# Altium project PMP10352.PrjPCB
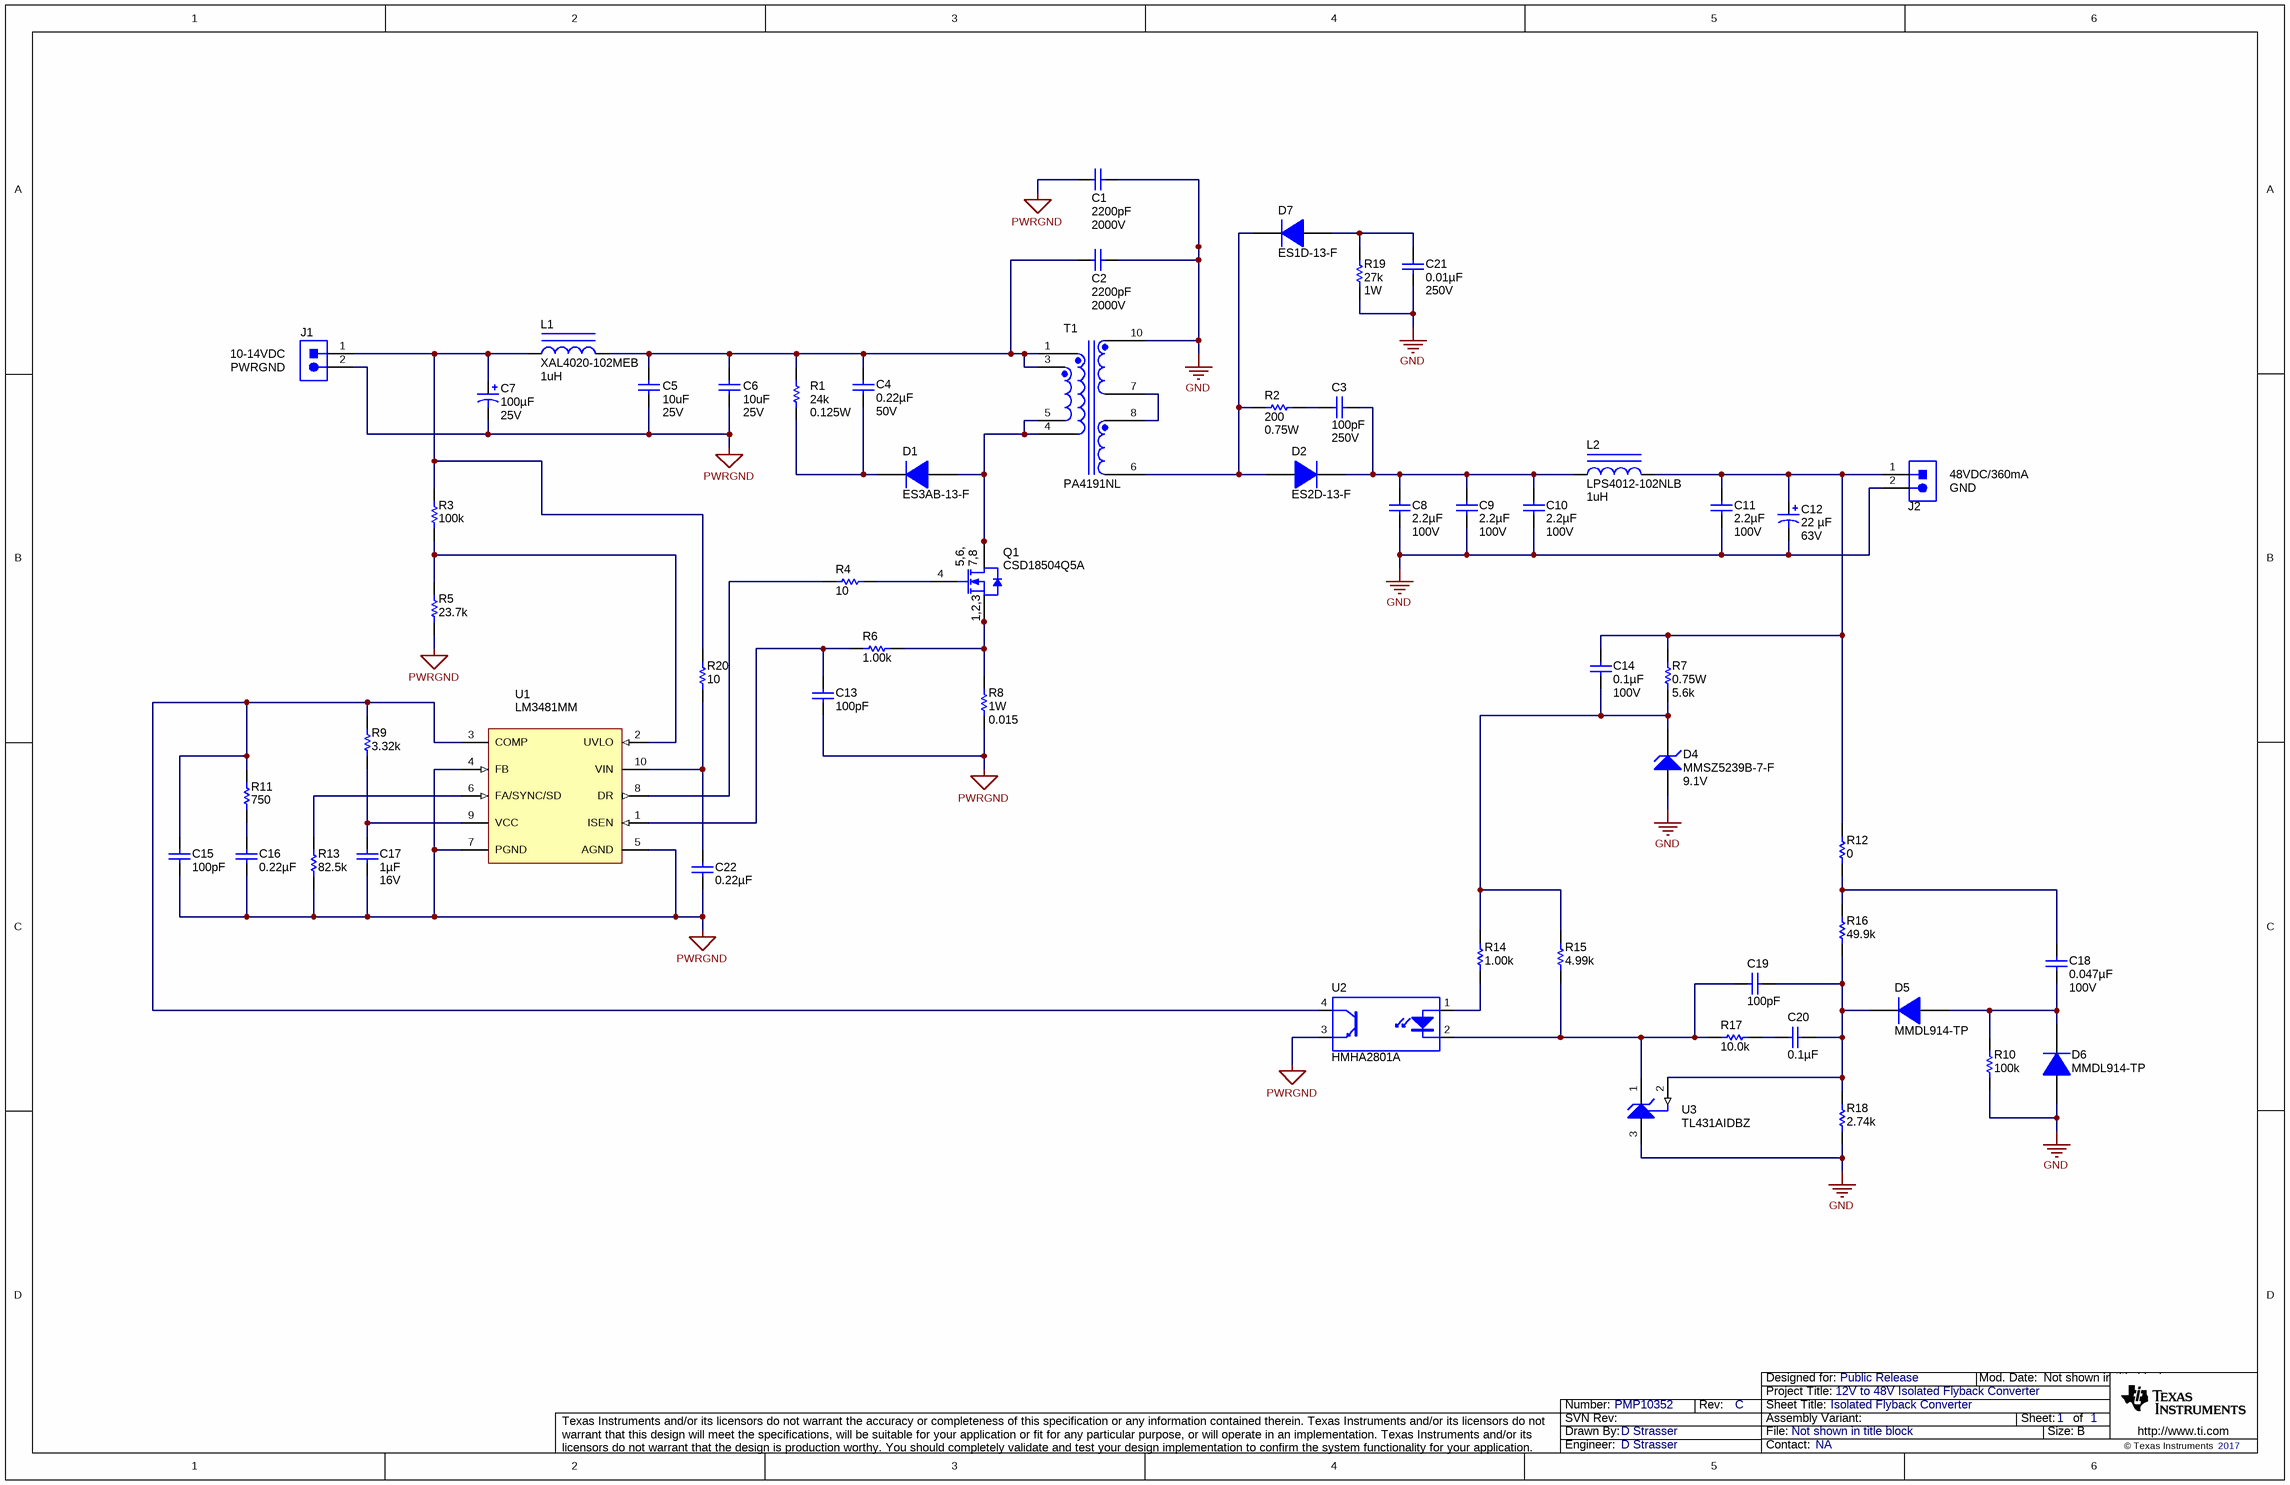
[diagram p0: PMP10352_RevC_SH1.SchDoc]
TechSupport: NA; SCH_Rev: C; PRJ_Title: 12V to 48V Isolated Flyback Converter; PRJ_Number: PMP10352; PRJ_Engineer: D Strasser; PRJ_Customer: Public Release; PCB_Rev: C; PCB_Layout: D Strasser; CopyrightYear: 2017
1 sheet, 57 parts. Net scope: global (net labels, ports and power ports of the same name join across sheets).
Board file: PMP10352_RevC.PcbDoc

## Sheet PMP10352_RevC_SH1.SchDoc: Isolated Flyback Converter
size 431 x 279 mm; Date: Not shown in title block; ApprovedBy: Not shown in title block; CheckedBy: Not shown in title block; Author: Not shown in title block; CompanyName: Not shown in title block; DrawnBy: D Strasser; Engineer: Not shown in title block; Organization: Not shown in title block; Address1: Not shown in title block; Address2: Not shown in title block; Address3: Not shown in title block; Address4: Not shown in title block; DocumentNumber: 1; Revision: Use project parameter SCH_Rev; SheetNumber: 1; SheetTotal: 1; PageSetup: Record=PageOptions¦CenterHorizontal=True¦CenterVertical=True¦PrintScale=1.00¦XCorrection=1.00¦YCorrection=1.00¦PrintKind=0¦BorderSize=5000000¦LeftOffset=0¦BottomOffset=0¦Orientation=2¦PaperLength=1000¦PaperWidth=1000¦Scale=100¦PaperSource=15¦PrintQuality=600¦MediaType=1¦DitherType=10¦PaperKind=Letter¦PrintScaleMode=1

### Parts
C1  ValueDisplayed: 2200pF  Value2: 2000V  [1812L]  (hidden comment: C4532X7R3D222K)
C2  ValueDisplayed: 2200pF  Value2: 2000V  [1812L]  (hidden comment: C4532X7R3D222K)
C3  ValueDisplayed: 100pF  Value2: 250V  [0805_HV]  (hidden comment: GRM21A5C2E101JW01D)
C4  ValueDisplayed: 0.22µF  Value2: 50V  [0805L]  (hidden comment: C2012X7R1H224K)
C5  value 10uF  Value2: 25V  [1210L]  (hidden comment: C3225X7R1E106K)
C6  value 10uF  Value2: 25V  [1210L]  (hidden comment: C3225X7R1E106K)
C7  ValueDisplayed: 100µF  Value2: 25V  [SM_RADIAL_D8]  (hidden comment: EEE-FK1E101XP)
C8  ValueDisplayed: 2.2µF  Value2: 100V  [1210L]  (hidden comment: GRM32ER72A225KA35L)
C9  ValueDisplayed: 2.2µF  Value2: 100V  [1210L]  (hidden comment: GRM32ER72A225KA35L)
C10  ValueDisplayed: 2.2µF  Value2: 100V  [1210L]  (hidden comment: GRM32ER72A225KA35L)
C11  ValueDisplayed: 2.2µF  Value2: 100V  [1210L]  (hidden comment: GRM32ER72A225KA35L)
C12  ValueDisplayed: 22 µF  Value2: 63V  [SM_RADIAL_D8]  (hidden comment: EEE-FK1J220XP)
C13  ValueDisplayed: 100pF  [0603L]  (hidden comment: C1608C0G1H101J)
C14  ValueDisplayed: 0.1µF  Value2: 100V  [0805_HV]  (hidden comment: C2012X7R2A104K125AA)
C15  ValueDisplayed: 100pF  [0603L]  (hidden comment: C1608C0G1H101J)
C16  ValueDisplayed: 0.22µF  [0603L]  (hidden comment: C1608X7R1E224K080AC)
C17  ValueDisplayed: 1µF  Value2: 16V  [0603L]  (hidden comment: C1608X7R1C105K080AC)
C18  ValueDisplayed: 0.047µF  Value2: 100V  [0805_HV]  (hidden comment: C2012X7R2A473K125AA)
C19  ValueDisplayed: 100pF  [0603L]  (hidden comment: C1608C0G1H101J)
C20  ValueDisplayed: 0.1µF  [0603L]  (hidden comment: C1608X7R1E104K080AA)
C21  ValueDisplayed: 0.01µF  Value2: 250V  [0805_HV]  (hidden comment: GRM21BR72E103KW03L)
C22  ValueDisplayed: 0.22µF  [0603L]  (hidden comment: C1608X7R1E224K080AC)
D1  ES3AB-13-F  [SMB]
D2  ES2D-13-F  [SMB]
D4  MMSZ5239B-7-F  value 9.1V  [SOD-123]
D5  MMDL914-TP  [sod-323]
D6  MMDL914-TP  [sod-323]
D7  ES1D-13-F  [SMA]
J1  PEC02SAAN  [CONN_PEC02SAAN]  (value not drawn)
J2  PEC02SAAN  [CONN_PEC02SAAN]  (value not drawn)
L1  XAL4020-102MEB  value 1uH  [XAL4020]
L2  LPS4012-102NLB  value 1uH  [LPS4012]
Q1  CSD18504Q5A  [TRANS_NexFET_Q5A]
R1  value 24k  Value2: 0.125W  [0805L]  (hidden comment: CRCW080524K0JNEA)
R2  value 200  Value2: 0.75W  [2010L]  (hidden comment: CRCW2010200RJNEF)
R3  value 100k  [0603L]  (hidden comment: CRCW0603100KFKEA)
R4  ValueDisplayed: 10  [0603]  (hidden comment: CRCW060310R0JNEA)
R5  value 23.7k  [0603L]  (hidden comment: CRCW060323K7FKEA)
R6  value 1.00k  [0603L]  (hidden comment: CRCW06031K00FKEA)
R7  Value2: 0.75W  ValueDisplayed: 5.6k  [2010]  (hidden comment: CRCW20105K60JNEF)
R8  Value2: 1W  ValueDisplayed: 0.015  [2010]  (hidden comment: CSRN2010FK15L0)
R9  value 3.32k  [0603L]  (hidden comment: CRCW06033K32FKEA)
R10  ValueDisplayed: 100k  [0603L]  (hidden comment: CRCW0603100KFKEA)
R11  ValueDisplayed: 750  [0603L]  (hidden comment: CRCW0603750RFKEA)
R12  value 0  [0603L]  (hidden comment: ERJ-3GEY0R00V)
R13  value 82.5k  [0603L]  (hidden comment: CRCW060382K5FKEA)
R14  value 1.00k  [0603L]  (hidden comment: CRCW06031K00FKEA)
R15  value 4.99k  [0603L]  (hidden comment: CRCW06034K99FKEA)
R16  value 49.9k  [0603L]  (hidden comment: CRCW060349K9FKEA)
R17  value 10.0k  [0603L]  (hidden comment: CRCW060310K0FKEA)
R18  value 2.74k  [0603L]  (hidden comment: CRCW06032K74FKEA)
R19  value 27k  Value2: 1W  [2512]  (hidden comment: CRCW251227K0JNEG)
R20  ValueDisplayed: 10  [0603L]  (hidden comment: CRCW060310R0JNEA)
T1  PA4191NL  [PULSE_PA4191NL]
U1  LM3481MM  [MUB10A_N]
U2  HMHA2801A  [MFP04A]
U3  TL431AIDBZ  [DBZ0003A_L]

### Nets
GND: C1.1 C2.1 C8.2 C9.2 C10.2 C11.2 C12.2(-) C21.2 D4.2(A) D6.2(A) J2.2 R10.1 R18.1 R19.1 T1.10 U3.3(ANODE)
PWRGND: C1.2 C5.2 C6.2 C7.2(-) C13.2 C15.2 C16.2 C17.2 C22.2 J1.2 R5.1 R8.1 R13.1 U1.4(FB) U1.5(AGND) U1.7(PGND) U2.3(E)
NetC2_2: C2.2 C4.1 C5.1 C6.1 L1.2 R1.2 T1.1 T1.3
NetC3_1: C3.1 C8.1 C9.1 C10.1 D2.1(K) L2.1
NetC3_2: C3.2 R2.2
NetC4_2: C4.2 D1.1(K) R1.1
NetC7_1: C7.1(+) J1.1 L1.1 R3.2 R20.2
NetC11_1: C11.1 C12.1(+) C14.1 J2.1 L2.2 R7.2 R12.2
NetC13_1: C13.1 R6.2 U1.1(ISEN)
NetC14_2: C14.2 D4.1(K) R7.1 R14.2 R15.2
NetC15_1: C15.1 R9.2 R11.2 U1.3(COMP) U2.4(C)
NetC16_1: C16.1 R11.1
NetC17_1: C17.1 R9.1 U1.9(VCC)
NetC18_1: C18.1 R12.1 R16.2
NetC18_2: C18.2 D5.2(A) D6.1(K) R10.2
NetC19_1: C19.1 C20.1 D5.1(K) R16.1 R18.2 U3.2(REF)
NetC19_2: C19.2 R15.1 R17.2 U2.2(K) U3.1(CATHODE)
NetC20_2: C20.2 R17.1
NetC21_1: C21.1 D7.2(A) R19.2
NetC22_1: C22.1 R20.1 U1.10(VIN)
NetD1_2: D1.2(A) Q1.5(D) Q1.6(D) Q1.7(D) Q1.8(D) Q1.9(D) T1.4 T1.5
NetD2_2: D2.2(A) D7.1(K) R2.1 T1.6
NetQ1_1: Q1.1(S) Q1.2(S) Q1.3(S) R6.1 R8.2
NetQ1_4: Q1.4(G) R4.2
NetR3_1: R3.1 R5.2 U1.2(UVLO)
NetR4_1: R4.1 U1.8(DR)
NetR13_2: R13.2 U1.6(FA/SYNC/SD)
NetR14_1: R14.1 U2.1(A)
NetT1_7: T1.7 T1.8

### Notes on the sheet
- (near J1) 10-14VDC
- (near J1) PWRGND
- (near J2) 48VDC/360mA
- (near J2) GND

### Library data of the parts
C1 C2 = C4532X7R3D222K: CAP, CERM, 2200pF, 2000V, +/-10%, X7R, 1812; Manufacturer: TDK; Polarized: N; CompType: Capacitor; U/M: EA; Cap_F: 0.0000000022; Tolerance_%: 10; Value1: Unknown; VDC_V: 2000; TaMin_C: -55; TaMax_C: 125; Cap_Case: 1812
C3 = GRM21A5C2E101JW01D: CAP, CERM, 100 pF, 250 V, +/- 5%, C0G/NP0, 0805; Manufacturer: MuRata; Polarized: N; CompType: Capacitor; Value: 100pF; U/M: EA; Cap_F: 0.0000000001; Tolerance_%: 5; Value1: Unknown; VDC_V: 250; TaMin_C: -55; TaMax_C: 125; Cap_Case: 0805
C4 = C2012X7R1H224K: CAP, CERM, 0.22uF, 50V, +/-10%, X7R, 0805; Manufacturer: TDK; Polarized: N; CompType: Capacitor; U/M: EA; Cap_F: 0.00000022; Tolerance_%: 10; ESR_Ohm: 0.0117; Value1: 0.0117 ohm; VDC_V: 50; TaMin_C: -55; TaMax_C: 125; Cap_Case: 0805
C5 C6 = C3225X7R1E106M: CAP, CERM, 10uF, 25V, +/-20%, X7R, 1210; Manufacturer: TDK; Polarized: N; CompType: Capacitor; ValueDisplayed: 10µF; U/M: EA; Cap_F: 0.00001; Tolerance_%: 20; ESR_Ohm: 0.0027; Value1: 0.0027 ohm; VDC_V: 25; IRMS_A: 3; TaMin_C: -55; TaMax_C: 125; Cap_Case: 1210
C7 = EEE-FK1E101XP: CAP, AL, 100uF, 25V, +/-20%, 0.34 ohm, SMD; Manufacturer: Panasonic; Polarized: Y; CompType: Capacitor; U/M: EA; Cap_F: 0.0001; Tolerance_%: 20; VDC_V: 25; ESR_Ohm: 0.34; IRMS_A: 0.28; TaMin_C: -55; TaMax_C: 105; Cap_Case: D8
C8-C11 = GRM32ER72A225KA35L: CAP, CERM, 2.2uF, 100V, +/-10%, X7R, 1210; Manufacturer: MuRata; Polarized: N; CompType: Capacitor; U/M: EA; Cap_F: 0.0000022; Tolerance_%: 10; ESR_Ohm: 0.007; Value1: 0.007 ohm; VDC_V: 100; IRMS_A: 4.4; TaMin_C: -55; TaMax_C: 125; Cap_Case: 1210
C12 = EEE-FK1J220XP: CAP, AL, 22uF, 63V, +/-20%, 1.2 ohm, SMD; Manufacturer: Panasonic; Polarized: Y; CompType: Capacitor; U/M: EA; Cap_F: 0.000022; Tolerance_%: 20; Value1: 1.2 ohm; VDC_V: 63; ESR_Ohm: 1.2; IRMS_A: 0.12; TaMin_C: -55; TaMax_C: 105; Cap_Case: D8
C13 C15 C19 = C1608C0G1H101J: CAP, CERM, 100pF, 50V, +/-5%, C0G/NP0, 0603; Manufacturer: TDK; Polarized: N; CompType: Capacitor; U/M: EA; Cap_F: 0.0000000001; Tolerance_%: 5; ESR_Ohm: 0.1679; Value1: 0.1679 ohm; VDC_V: 50; TaMin_C: -55; TaMax_C: 125; Cap_Case: 0603
C14 = C2012X7R2A104K125AA: CAP, CERM, 0.1 µF, 100 V,+/- 10%, X7R, 0805; Manufacturer: TDK; Polarized: N; CompType: Capacitor; Value: 0.1uF; U/M: EA; Cap_F: 0.0000001; Tolerance_%: 10; ESR_ohm: 0.020726; Value1: 0.020726 ohm; VDC_V: 100; IRMS_A: 1.456; TaMin_C: -55; TaMax_C: 125; Cap_Case: 0805; SizeArea_mm2: 2.5; SizeAreaWB_mm2: 6.75; SizeX_mm: 2; SizeY_mm: 1.25; SizeZ_mm: 1.45; AEC Category: Q200; Green_Lifecycle: Active; Green_REACh: Passed
C16 C22 = C1608X7R1E224K080AC: CAP, CERM, 0.22 µF, 25 V,+/- 10%, X7R, 0603; Manufacturer: TDK; Polarized: N; CompType: Capacitor; Value: 0.22uF; U/M: EA; Cap_F: 0.00000022; Tolerance_%: 10; VDC_V: 25; Value2: 25V; TaMin_C: -55; TaMax_C: 125; Cap_Case: 0603; SizeArea_mm2: 1.28; SizeAreaWB_mm2: 4.68; SizeX_mm: 1.6; SizeY_mm: 0.8; SizeZ_mm: 1; AEC Category: Q200
C17 = C1608X7R1C105K080AC: CAP, CERM, 1 µF, 16 V,+/- 10%, X7R, 0603; Manufacturer: TDK; Polarized: N; CompType: Capacitor; Value: 1uF; U/M: EA; Cap_F: 0.000001; Tolerance_%: 10; ESR_ohm: 0.0057; Value1: 0.0057 ohm; VDC_V: 16; TaMin_C: -55; TaMax_C: 125; Cap_Case: 0603; SizeArea_mm2: 1.28; SizeAreaWB_mm2: 4.68; SizeX_mm: 1.6; SizeY_mm: 0.8; SizeZ_mm: 1; AEC Category: Q200; Green_Lifecycle: Active; Green_REACh: Passed
C18 = C2012X7R2A473K125AA: CAP, CERM, 0.047 µF, 100 V,+/- 10%, X7R, 0805; Manufacturer: TDK; Polarized: N; CompType: Capacitor; Value: 0.047uF; U/M: EA; Cap_F: 0.000000047; Tolerance_%: 10; ESR_ohm: 0.049089; Value1: 0.049089 ohm; VDC_V: 100; IRMS_A: 0.963171; TaMin_C: -55; TaMax_C: 125; Cap_Case: 0805; SizeArea_mm2: 2.5; SizeAreaWB_mm2: 6.75; SizeX_mm: 2; SizeY_mm: 1.25; SizeZ_mm: 1.45; AEC Category: Q200
C20 = C1608X7R1E104K080AA: CAP, CERM, 0.1 µF, 25 V,+/- 10%, X7R, 0603; Manufacturer: TDK; Polarized: N; CompType: Capacitor; Value: 0.1uF; U/M: EA; Cap_F: 0.0000001; Tolerance_%: 10; VDC_V: 25; Value2: 25V; TaMin_C: -55; TaMax_C: 125; Cap_Case: 0603; SizeArea_mm2: 1.28; SizeAreaWB_mm2: 4.68; SizeX_mm: 1.6; SizeY_mm: 0.8; SizeZ_mm: 1; AEC Category: Q200; Green_Lifecycle: NRND; Green_REACh: Passed
C21 = GRM21BR72E103KW03L: CAP, CERM, 0.01 µF, 250 V,+/- 10%, X7R, 0805; Manufacturer: MuRata; Polarized: N; CompType: Capacitor; Value: 0.01uF; U/M: EA; Cap_F: 0.00000001; Tolerance_%: 10; VDC_V: 250; TaMin_C: -55; TaMax_C: 125; Cap_Case: 0805; SizeArea_mm2: 2.5; SizeAreaWB_mm2: 6.75; SizeX_mm: 2; SizeY_mm: 1.25; SizeZ_mm: 1.45; AEC Category: Q200; Green_Lifecycle: Not Set; Green_REACh: Incomplete
D1 = ES3AB-13-F: Diode, Superfast Rectifier, 50V, 3A, SMB; Manufacturer: Diodes Inc.; U/M: EA; Vf_V: 0.9; Value2: 0.9V; Io_A: 3; Vr_V: 50; TJmax_C: 150; RJC_CperW: 10
D2 = ES2D-13-F: Diode, Ultrafast, 200V, 2A, SMB; Manufacturer: Diodes Inc.; U/M: EA; Vf_V: 0.92; Value2: 0.92V; Io_A: 2; Vr_V: 200; TJmax_C: 150; RJC_CperW: 20
D4 = MMSZ5239B-7-F: Diode, Zener, 9.1V, 500mW, SOD-123; Manufacturer: Diodes Inc.; SymbolCreator: a0412235; U/M: EA; Power_W: 0.5; Vz_V: 9.1; Value1: 0.5W; RJA_CperW: 350
D5 D6 = MMDL914-TP: Diode, Switching, 100V, 0.2A, SOD-323; Manufacturer: Micro Commercial Components; U/M: EA; Vf_V: 1; Value2: 1V; Io_A: 0.2; Vr_V: 100; TJmax_C: 150; RJC_CperW: 635
D7 = ES1D-13-F: Diode, Ultrafast, 200V, 1A, SMA; Manufacturer: Diodes Inc.; U/M: EA; Vf_V: 0.92; Value2: 0.92V; Io_A: 1; Vr_V: 200; TJmax_C: 150; RJC_CperW: 25
J1 J2 = PEC02SAAN: Header, 100mil, 2x1, Tin, TH; Manufacturer: Sullins Connector Solutions; SymbolCreator: a0412235; U/M: EA
L1 = XAL4020-102MEB: Inductor, Shielded, Composite, 1uH, 8.75A, 0.01 ohm, SMD; Manufacturer: Coilcraft; Ind_H: 1.0E-6; ValueDisplayed: 1µH; Imax_A: 8.75; Irms: 9.6A @ 40C rise; Isat: 8.75A @ 30% inductance drop; DCR_ohm: 0.01
L2 = LPS4012-102NLB: Inductor, Shielded Drum Core, Ferrite, 1uH, 2.4A, 0.06 ohm, SMD; Manufacturer: Coilcraft; Ind_H: 1.0E-6; ValueDisplayed: 1µH; Imax_A: 2.4; Irms: 2.4A @ 40C rise; Isat: 3A @ 30% inductance drop; DCR_ohm: 0.06
Q1 = CSD18504Q5A: MOSFET, N-CH, 40V, 15A, SON 5x6mm; Manufacturer: Texas Instruments; Alternate Manufacturer: None; U/M: EA; ChType: N; VdsMax_V: 40; Value1: 0.0098 ohm; Rdson45_Ohm: 0.0098; Value2: 7.7 nC; QgTyp_nC: 7.7; Vgs_V: 20; IdsMax_A: 15
R1 = CRCW080524K0JNEA: RES, 24k ohm, 5%, 0.125W, 0805; Manufacturer: Vishay-Dale; CompType: Resistor; Res_ohm: 24000; Value_Code: 24k0; Tolerance_%: 5; Power_W: 0.125; VDC_V: 150; TempCo: 200 ppm/C; EIA_Code: E24; U/M: EA
R2 = CRCW2010200RJNEF: RES, 200 ohm, 5%, 0.75W, 2010; Manufacturer: Vishay-Dale; CompType: Resistor; Value_Code: 200R; Tolerance_%: 5; Power_W: 0.75; VDC_V: 400; TempCo: 200 ppm/C; EIA_Code: E24; U/M: EA
R3 = CRCW0603100KFKEA: RES, 100k ohm, 1%, 0.1W, 0603; Manufacturer: Vishay-Dale; CompType: Resistor; Res_ohm: 100000; Tolerance_%: 1; Power_W: 0.1; VDC_V: 75; TempCo: 100 ppm/C; EIA_Code: E96; U/M: EA
R4 R20 = CRCW060310R0JNEA: RES, 10, 5%, 0.1 W, 0603; Manufacturer: Vishay-Dale; CompType: Resistor; Value: 10; Value_Code: 10R0; Tolerance_%: 5; Power_W: 0.1; Value2: 0.1W; VDC_V: 75; TempCo: 200 ppm/C; EIA_Code: E24; U/M: EA; SizeArea_mm2: 1.28; SizeX_mm: 1.6; SizeY_mm: 0.8; SizeZ_mm: 1; AEC Category: Q200; Green_Lifecycle: Active; Green_REACh: Passed
R5 = CRCW060323K7FKEA: RES, 23.7k ohm, 1%, 0.1W, 0603; Manufacturer: Vishay-Dale; CompType: Resistor; Res_ohm: 23700; Value_Code: 23k7; Tolerance_%: 1; Power_W: 0.1; VDC_V: 75; TempCo: 100 ppm/C; EIA_Code: E96; U/M: EA
R6 R14 = CRCW06031K00FKEA: RES, 1.00k ohm, 1%, 0.1W, 0603; Manufacturer: Vishay-Dale; CompType: Resistor; Res_ohm: 1000; Value_Code: 1k00; Tolerance_%: 1; Power_W: 0.1; VDC_V: 75; TempCo: 100 ppm/C; EIA_Code: E96; U/M: EA
R7 = CRCW20105K60JNEF: RES, 5.6 k, 5%, 0.75 W, AEC-Q200 Grade 0, 2010; Manufacturer: Vishay-Dale; CompType: Resistor; Value: 5.6k; Res_ohm: 5600; Value_Code: 5k60; Tolerance_%: 5; Power_W: 0.75; VDC_V: 400; TempCo: 200 ppm/C; EIA_Code: E24; U/M: EA; SizeArea_mm2: 12.5; SizeY_mm: 2.5; SizeZ_mm: 1.66; AEC Category: Q200; AEC Qualified: Y; AEC Grade: 0
R8 = CSRN2010FK15L0: RES, 0.015, 1%, 1 W, 2010; Manufacturer: Stackpole Electronics Inc; CompType: Resistor; Value: 0.015; Value_Code: R015; Tolerance_%: 1; TempCo: 250 ppm/C; EIA_Code: E96; U/M: EA; SizeArea_mm2: 12.5; SizeX_mm: 5; SizeY_mm: 2.5; SizeZ_mm: 1.66; AEC Category: Q200
R9 = CRCW06033K32FKEA: RES, 3.32k ohm, 1%, 0.1W, 0603; Manufacturer: Vishay-Dale; CompType: Resistor; Res_ohm: 3320; Value_Code: 3k32; Tolerance_%: 1; Power_W: 0.1; VDC_V: 75; TempCo: 100 ppm/C; EIA_Code: E96; U/M: EA
R10 = CRCW0603100KFKEA: RES, 100 k, 1%, 0.1 W, 0603; Manufacturer: Vishay-Dale; CompType: Resistor; Value: 100k; Res_ohm: 100000; Tolerance_%: 1; Power_W: 0.1; Value2: 0.1W; VDC_V: 75; TempCo: 100 ppm/C; EIA_Code: E96; U/M: EA; SizeArea_mm2: 1.28; SizeX_mm: 1.6; SizeY_mm: 0.8; AEC Category: Q200; Green_Lifecycle: Active; Green_REACh: Passed
R11 = CRCW0603750RFKEA: RES, 750, 1%, 0.1 W, 0603; Manufacturer: Vishay-Dale; CompType: Resistor; Value_Code: 750R; Tolerance_%: 1; Power_W: 0.1; Value2: 0.1W; VDC_V: 75; TempCo: 100 ppm/C; EIA_Code: E96; U/M: EA; Value: 750
R12 = ERJ-3GEY0R00V: RES, 0 ohm, 5%, 0.1W, 0603; Manufacturer: Panasonic; CompType: Resistor; Value_Code: 0000; Tolerance_%: 5; Power_W: 0.1; VDC_V: 50; TempCo: 600 ppm/C; EIA_Code: E24; U/M: EA
R13 = CRCW060382K5FKEA: RES, 82.5k ohm, 1%, 0.1W, 0603; Manufacturer: Vishay-Dale; CompType: Resistor; Res_ohm: 82500; Value_Code: 82k5; Tolerance_%: 1; Power_W: 0.1; VDC_V: 75; TempCo: 100 ppm/C; EIA_Code: E96; U/M: EA
R15 = CRCW06034K99FKEA: RES, 4.99k ohm, 1%, 0.1W, 0603; Manufacturer: Vishay-Dale; CompType: Resistor; Res_ohm: 4990; Value_Code: 4k99; Tolerance_%: 1; Power_W: 0.1; VDC_V: 75; TempCo: 100 ppm/C; EIA_Code: E96; U/M: EA
R16 = CRCW060349K9FKEA: RES, 49.9k ohm, 1%, 0.1W, 0603; Manufacturer: Vishay-Dale; CompType: Resistor; Res_ohm: 49900; Value_Code: 49k9; Tolerance_%: 1; Power_W: 0.1; VDC_V: 75; TempCo: 100 ppm/C; EIA_Code: E96; U/M: EA
R17 = CRCW060310K0FKEA: RES, 10.0k ohm, 1%, 0.1W, 0603; Manufacturer: Vishay-Dale; CompType: Resistor; Res_ohm: 10000; Value_Code: 10k0; Tolerance_%: 1; Power_W: 0.1; VDC_V: 75; TempCo: 100 ppm/C; EIA_Code: E96; U/M: EA
R18 = CRCW06032K74FKEA: RES, 2.74k ohm, 1%, 0.1W, 0603; Manufacturer: Vishay-Dale; CompType: Resistor; Res_ohm: 2740; Value_Code: 2k74; Tolerance_%: 1; Power_W: 0.1; VDC_V: 75; TempCo: 100 ppm/C; EIA_Code: E96; U/M: EA
R19 = CRCW251227K0JNEG: RES, 27k ohm, 5%, 1W, 2512; Manufacturer: Vishay-Dale; CompType: Resistor; Res_ohm: 27000; Value_Code: 27k0; Tolerance_%: 5; Power_W: 1; VDC_V: 500; TempCo: 200 ppm/C; EIA_Code: E24; U/M: EA
T1 = PA4191NL: Transformer, 10 uH, SMT; Manufacturer: Pulse Engineering; SymbolCreator: Altium; DCR_Ohm: 0.02; Value: 10 uH; U/M: EA
U1 = LM3481MM: High Efficiency Low-Side N-Channel Controller for Switching Regulators, 10-pin MSOP; Manufacturer: National Semiconductor; PackageTopMarking: ZXTT*SJPB; PowerWise: N; CompType: MiscPower
U2 = HMHA2801A: Optocoupler, 3.75kV RMS, SMT; Manufacturer: Fairchild Semiconductor; U/M: EA
U3 = TL431AIDBZ: PRECISION PROGRAMMABLE REFERENCE, DBZ0003A; Alternate Manufacturer: None; Manufacturer: Texas Instruments; SymbolCreator: a0412235; CompType: IC; U/M: EA

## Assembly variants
001: not fitted FID1 FID2 FID3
